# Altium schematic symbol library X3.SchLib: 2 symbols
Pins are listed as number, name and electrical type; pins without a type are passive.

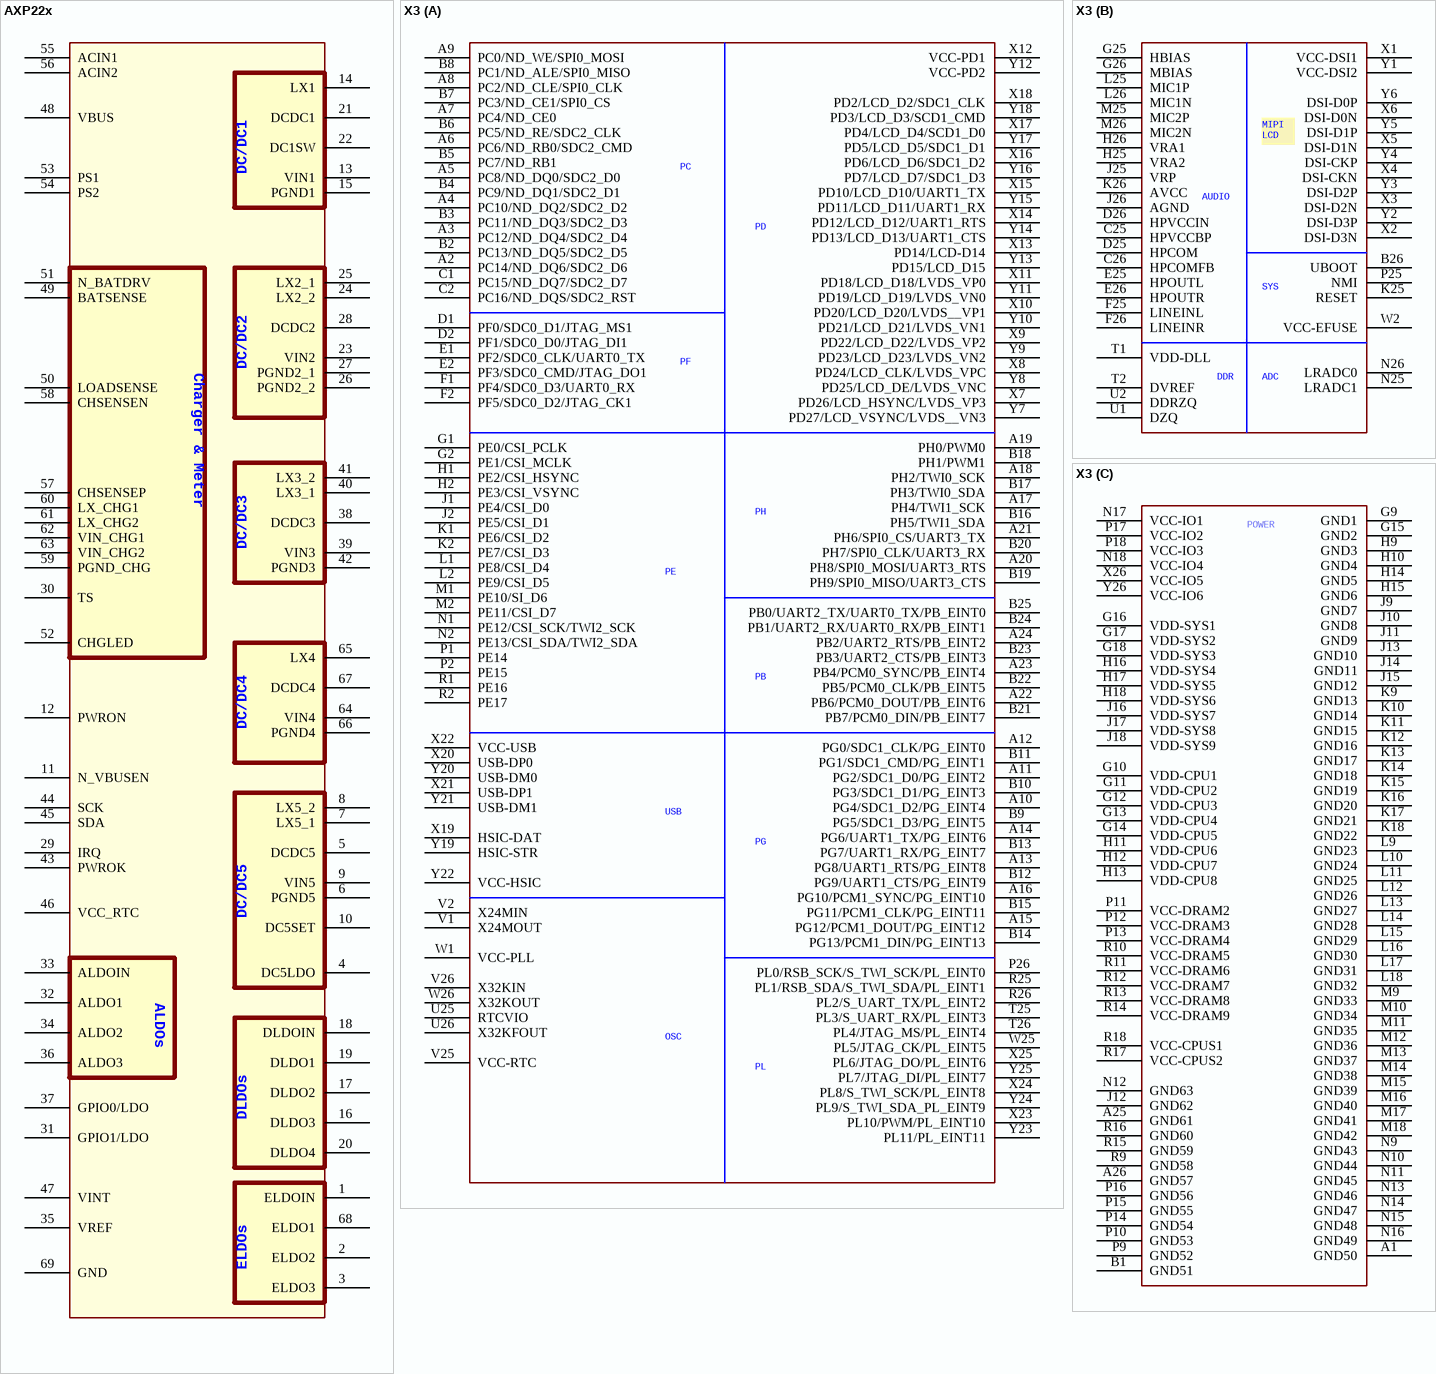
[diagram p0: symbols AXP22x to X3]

## AXP22x
designator U?
pins: 1 ELDOIN, 2 ELDO2, 3 ELDO3, 4 DC5LDO, 5 DCDC5, 6 PGND5, 7 LX5_1, 8 LX5_2, 9 VIN5, 10 DC5SET, 11 N_VBUSEN, 12 PWRON, 13 VIN1, 14 LX1, 15 PGND1, 16 DLDO3, 17 DLDO2, 18 DLDOIN, 19 DLDO1, 20 DLDO4, 21 DCDC1, 22 DC1SW, 23 VIN2, 24 LX2_2, 25 LX2_1, 26 PGND2_2, 27 PGND2_1, 28 DCDC2, 29 IRQ, 30 TS, 31 GPIO1/LDO, 32 ALDO1, 33 ALDOIN, 34 ALDO2, 35 VREF, 36 ALDO3, 37 GPIO0/LDO, 38 DCDC3, 39 VIN3, 40 LX3_1, 41 LX3_2, 42 PGND3, 43 PWROK, 44 SCK, 45 SDA, 46 VCC_RTC, 47 VINT, 48 VBUS, 49 BATSENSE, 50 LOADSENSE, 51 N_BATDRV, 52 CHGLED, 53 PS1, 54 PS2, 55 ACIN1, 56 ACIN2, 57 CHSENSEP, 58 CHSENSEN, 59 PGND_CHG, 60 LX_CHG1, 61 LX_CHG2, 62 VIN_CHG1, 63 VIN_CHG2, 64 VIN4, 65 LX4, 66 PGND4, 67 DCDC4, 68 ELDO1, 69 GND

## X3
designator U?  (value not drawn)
part A pins: A2 PC14/ND_DQ6/SDC2_D6, A3 PC12/ND_DQ4/SDC2_D4, A4 PC10/ND_DQ2/SDC2_D2, A5 PC8/ND_DQ0/SDC2_D0, A6 PC6/ND_RB0/SDC2_CMD, A7 PC4/ND_CE0, A8 PC2/ND_CLE/SPI0_CLK, A9 PC0/ND_WE/SPI0_MOSI, A10 PG4/SDC1_D2/PG_EINT4, A11 PG2/SDC1_D0/PG_EINT2, A12 PG0/SDC1_CLK/PG_EINT0, A13 PG8/UART1_RTS/PG_EINT8, A14 PG6/UART1_TX/PG_EINT6, A15 PG12/PCM1_DOUT/PG_EINT12, A16 PG10/PCM1_SYNC/PG_EINT10, A17 PH4/TWI1_SCK, A18 PH2/TWI0_SCK, A19 PH0/PWM0, A20 PH8/SPI0_MOSI/UART3_RTS, A21 PH6/SPI0_CS/UART3_TX, A22 PB6/PCM0_DOUT/PB_EINT6, A23 PB4/PCM0_SYNC/PB_EINT4, A24 PB2/UART2_RTS/PB_EINT2, B2 PC13/ND_DQ5/SDC2_D5, B3 PC11/ND_DQ3/SDC2_D3, B4 PC9/ND_DQ1/SDC2_D1, B5 PC7/ND_RB1, B6 PC5/ND_RE/SDC2_CLK, B7 PC3/ND_CE1/SPI0_CS, B8 PC1/ND_ALE/SPI0_MISO, B9 PG5/SDC1_D3/PG_EINT5, B10 PG3/SDC1_D1/PG_EINT3, B11 PG1/SDC1_CMD/PG_EINT1, B12 PG9/UART1_CTS/PG_EINT9, B13 PG7/UART1_RX/PG_EINT7, B14 PG13/PCM1_DIN/PG_EINT13, B15 PG11/PCM1_CLK/PG_EINT11, B16 PH5/TWI1_SDA, B17 PH3/TWI0_SDA, B18 PH1/PWM1, B19 PH9/SPI0_MISO/UART3_CTS, B20 PH7/SPI0_CLK/UART3_RX, B21 PB7/PCM0_DIN/PB_EINT7, B22 PB5/PCM0_CLK/PB_EINT5, B23 PB3/UART2_CTS/PB_EINT3, B24 PB1/UART2_RX/UART0_RX/PB_EINT1, B25 PB0/UART2_TX/UART0_TX/PB_EINT0, C1 PC15/ND_DQ7/SDC2_D7, C2 PC16/ND_DQS/SDC2_RST, D1 PF0/SDC0_D1/JTAG_MS1, D2 PF1/SDC0_D0/JTAG_DI1, E1 PF2/SDC0_CLK/UART0_TX, E2 PF3/SDC0_CMD/JTAG_DO1, F1 PF4/SDC0_D3/UART0_RX, F2 PF5/SDC0_D2/JTAG_CK1, G1 PE0/CSI_PCLK, G2 PE1/CSI_MCLK, H1 PE2/CSI_HSYNC, H2 PE3/CSI_VSYNC, J1 PE4/CSI_D0, J2 PE5/CSI_D1, K1 PE6/CSI_D2, K2 PE7/CSI_D3, L1 PE8/CSI_D4, L2 PE9/CSI_D5, M1 PE10/SI_D6, M2 PE11/CSI_D7, N1 PE12/CSI_SCK/TWI2_SCK, N2 PE13/CSI_SDA/TWI2_SDA, P1 PE14, P2 PE15, P26 PL0/RSB_SCK/S_TWI_SCK/PL_EINT0, R1 PE16, R2 PE17, R25 PL1/RSB_SDA/S_TWI_SDA/PL_EINT1, R26 PL2/S_UART_TX/PL_EINT2, T25 PL3/S_UART_RX/PL_EINT3, T26 PL4/JTAG_MS/PL_EINT4, U25 RTCVIO, U26 X32KFOUT, V1 X24MOUT, V2 X24MIN, V25 VCC-RTC, V26 X32KIN, W1 VCC-PLL, W25 PL5/JTAG_CK/PL_EINT5, W26 X32KOUT, X7 PD26/LCD_HSYNC/LVDS_VP3, X8 PD24/LCD_CLK/LVDS_VPC, X9 PD22/LCD_D22/LVDS_VP2, X10 PD20/LCD_D20/LVDS__VP1, X11 PD18/LCD_D18/LVDS_VP0, X12 VCC-PD1, X13 PD14/LCD-D14, X14 PD12/LCD_D12/UART1_RTS, X15 PD10/LCD_D10/UART1_TX, X16 PD6/LCD_D6/SDC1_D2, X17 PD4/LCD_D4/SCD1_D0, X18 PD2/LCD_D2/SDC1_CLK, X19 HSIC-DAT, X20 USB-DP0, X21 USB-DP1, X22 VCC-USB, X23 PL10/PWM/PL_EINT10, X24 PL8/S_TWI_SCK/PL_EINT8, X25 PL6/JTAG_DO/PL_EINT6, Y7 PD27/LCD_VSYNC/LVDS__VN3, Y8 PD25/LCD_DE/LVDS_VNC, Y9 PD23/LCD_D23/LVDS_VN2, Y10 PD21/LCD_D21/LVDS_VN1, Y11 PD19/LCD_D19/LVDS_VN0, Y12 VCC-PD2, Y13 PD15/LCD_D15, Y14 PD13/LCD_D13/UART1_CTS, Y15 PD11/LCD_D11/UART1_RX, Y16 PD7/LCD_D7/SDC1_D3, Y17 PD5/LCD_D5/SDC1_D1, Y18 PD3/LCD_D3/SCD1_CMD, Y19 HSIC-STR, Y20 USB-DM0, Y21 USB-DM1, Y22 VCC-HSIC, Y23 PL11/PL_EINT11, Y24 PL9/S_TWI_SDA_PL_EINT9, Y25 PL7/JTAG_DI/PL_EINT7
part B pins: B26 UBOOT, C25 HPVCCBP, C26 HPCOMFB, D25 HPCOM, D26 HPVCCIN, E25 HPOUTL, E26 HPOUTR, F25 LINEINL, F26 LINEINR, G25 HBIAS, G26 MBIAS, H25 VRA2, H26 VRA1, J25 VRP, J26 AGND, K25 RESET, K26 AVCC, L25 MIC1P, L26 MIC1N, M25 MIC2P, M26 MIC2N, N25 LRADC1, N26 LRADC0, P25 NMI, T1 VDD-DLL, T2 DVREF, U1 DZQ, U2 DDRZQ, W2 VCC-EFUSE, X1 VCC-DSI1, X2 DSI-D3N, X3 DSI-D2N, X4 DSI-CKN, X5 DSI-D1N, X6 DSI-D0N, Y1 VCC-DSI2, Y2 DSI-D3P, Y3 DSI-D2P, Y4 DSI-CKP, Y5 DSI-D1P, Y6 DSI-D0P
part C pins: A1 GND50, A25 GND61, A26 GND57, B1 GND51, G9 GND1, G10 VDD-CPU1, G11 VDD-CPU2, G12 VDD-CPU3, G13 VDD-CPU4, G14 VDD-CPU5, G15 GND2, G16 VDD-SYS1, G17 VDD-SYS2, G18 VDD-SYS3, H9 GND3, H10 GND4, H11 VDD-CPU6, H12 VDD-CPU7, H13 VDD-CPU8, H14 GND5, H15 GND6, H16 VDD-SYS4, H17 VDD-SYS5, H18 VDD-SYS6, J9 GND7, J10 GND8, J11 GND9, J12 GND62, J13 GND10, J14 GND11, J15 GND12, J16 VDD-SYS7, J17 VDD-SYS8, J18 VDD-SYS9, K9 GND13, K10 GND14, K11 GND15, K12 GND16, K13 GND17, K14 GND18, K15 GND19, K16 GND20, K17 GND21, K18 GND22, L9 GND23, L10 GND24, L11 GND25, L12 GND26, L13 GND27, L14 GND28, L15 GND29, L16 GND30, L17 GND31, L18 GND32, M9 GND33, M10 GND34, M11 GND35, M12 GND36, M13 GND37, M14 GND38, M15 GND39, M16 GND40, M17 GND41, M18 GND42, N9 GND43, N10 GND44, N11 GND45, N12 GND63, N13 GND46, N14 GND47, N15 GND48, N16 GND49, N17 VCC-IO1, N18 VCC-IO4, P9 GND52, P10 GND53, P11 VCC-DRAM2, P12 VCC-DRAM3, P13 VCC-DRAM4, P14 GND54, P15 GND55, P16 GND56, P17 VCC-IO2, P18 VCC-IO3, R9 GND58, R10 VCC-DRAM5, R11 VCC-DRAM6, R12 VCC-DRAM7, R13 VCC-DRAM8, R14 VCC-DRAM9, R15 GND59, R16 GND60, R17 VCC-CPUS2, R18 VCC-CPUS1, X26 VCC-IO5, Y26 VCC-IO6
